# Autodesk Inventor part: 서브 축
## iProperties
Company: 한국ATC센터
Created: 2014-10
Part Number: 서브 축
Document SubType Name: Modeling
Designer: KYOUNG IL JANG
Density: 1 g/cm^3
Mass: 19.9624 g
Surface Area: 57.7178 cm^2
Volume: 19.9624 cm^3
Author: KYOUNG IL JANG
Revision Number: 1
